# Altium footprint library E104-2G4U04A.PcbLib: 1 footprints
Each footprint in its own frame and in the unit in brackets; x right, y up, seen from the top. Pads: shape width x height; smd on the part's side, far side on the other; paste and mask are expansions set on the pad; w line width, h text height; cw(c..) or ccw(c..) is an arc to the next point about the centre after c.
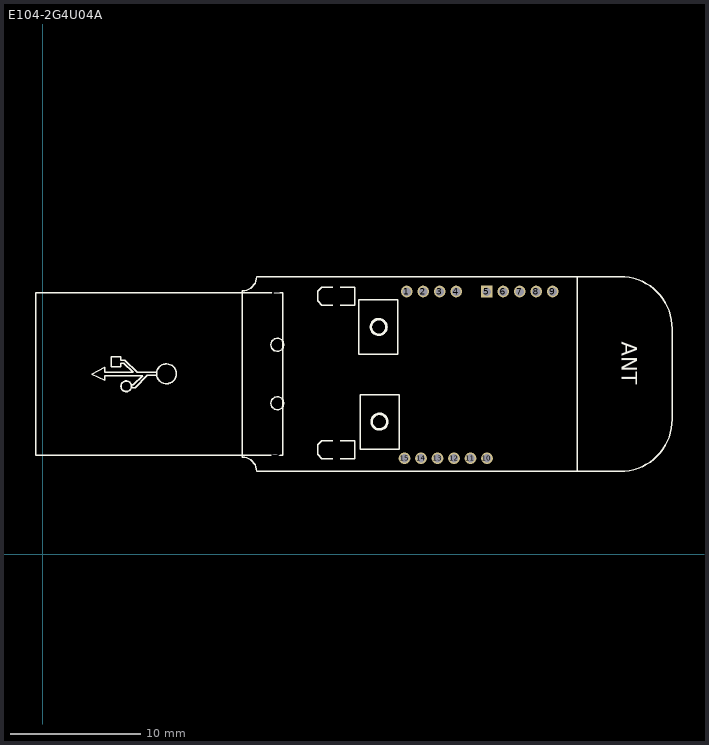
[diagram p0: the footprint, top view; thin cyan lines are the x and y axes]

## E104-2G4U04A [mm]
pads (17):
  round 0.9 hole 0.65: 1(28.035,20.234) 2(29.305,20.234) 3(30.575,20.234) 4(31.845,20.234) 6(35.465,20.234) 7(36.735,20.234) 8(38.005,20.234) 9(39.275,20.234) 10(34.215,7.394) 11(32.945,7.394) 12(31.675,7.394) 13(30.405,7.394) 14(29.135,7.394) 15(27.865,7.394)
  oval 3.5x2 on Top Overlay: 5(18.075,8.034) 5(18.075,19.734)
  rect 0.9x0.9 hole 0.65: 5(34.195,20.234)
Top Overlay:
  circle w0.127: c6.437,12.937 r0.406
  circle w0.127: c9.536,13.902 r0.762
  circle w0.2: c25.935,10.214 r0.6
  circle w0.2: c25.875,17.504 r0.6
  circle w0.1: c18.075,16.134 r0.5
  circle w0.1: c18.075,11.634 r0.5
  lines w0.1: 6.818,12.836 7.123,12.836 8.062,13.775 8.799,13.775 ; 6.818,13.039 6.996,13.039 7.707,13.75 4.786,13.75 4.786,13.394 3.795,13.877 4.786,14.385 4.786,14.004 6.97,14.004 6.259,14.715 6.03,14.715 6.03,14.461 5.294,14.461 5.294,15.198 6.03,15.198 6.03,14.944 6.335,14.944 7.275,14.004 8.799,14.004 ; 21.203,7.658 21.203,8.442 21.491,8.73 22.346,8.73 ; 21.203,19.478 21.203,20.262 21.491,20.55 22.346,20.55 ; 21.205,7.654 21.495,7.364 ; 21.205,19.474 21.495,19.184 ; 21.503,7.358 22.346,7.358 ; 21.503,19.178 22.346,19.178 ; 22.904,7.358 24.047,7.358 24.047,8.73 22.904,8.73 ; 22.904,19.178 24.047,19.178 24.047,20.55 22.904,20.55 ; 41.148,6.384 41.148,16.764 41.148,21.384 ; -0.525,7.634 18.475,7.634 18.475,20.134 -0.525,20.134 -0.525,7.634 ; 15.375,7.484 cw(c15.375,6.384) 16.475,6.384 19.375,6.384 44.475,6.384 ccw(c44.475,10.384) 48.475,10.384 48.475,17.384 ccw(c44.475,17.384) 44.475,21.384 19.375,21.384 16.475,21.384 cw(c15.375,21.384) 15.375,20.284 15.375,19.084 15.375,8.684 15.375,7.484 ; 24.355,15.414 27.355,15.414 27.355,19.614 24.355,19.614 24.355,15.414 ; 24.455,8.104 27.455,8.104 27.455,12.304 24.455,12.304 24.455,8.104
  text "ANT" at 44.196,16.383 h2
